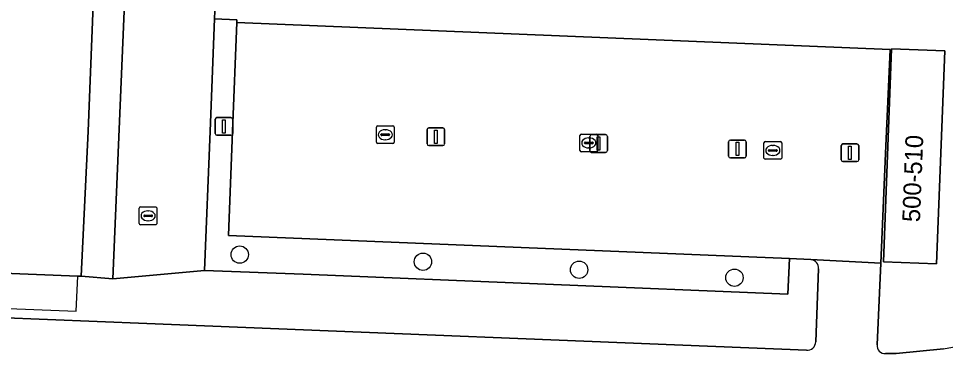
# Model space of a CAD drawing. Extents: x 160888 to 161385, y 386490 to 386908.
# Drawn here: x 160947.8 to 161000.1, y 386737.3 to 386756.3 of the extents above; entities that cross this region are included whole.
import ezdxf

# ---------------------------------------------------------------- set-up
doc = ezdxf.new("R2010")
doc.units = 0
for name, color, linetype in [('IMGEO_Boom', 7, 'Continuous'), ('IMGEO_Fietspad_gesloten', 7, 'Continuous'), ('IMGEO_Groenvoorziening', 7, 'Continuous'), ('IMGEO_Haag', 7, 'Continuous'), ('IMGEO_Kolk', 7, 'Continuous'), ('IMGEO_Lichtmast', 7, 'Continuous'), ('IMGEO_Pand', 7, 'Continuous'), ('IMGEO_Pand_nummerreeks', 7, 'Continuous'), ('IMGEO_Pand_overbouw', 7, 'Continuous'), ('IMGEO_Parkeervlak_open', 7, 'Continuous'), ('IMGEO_Voetpad_gesloten', 7, 'Continuous'), ('IMGEO_Voetpad_open', 7, 'Continuous')]:
    doc.layers.add(name, color=color, linetype=linetype)

msp = doc.modelspace()

# ---------------------------------------------------------------- linework, layer by layer
at = {"layer": 'IMGEO_Boom'}
for centre in [(160960.32, 386743.054), (160970.655, 386742.654), (160979.462, 386742.2), (160988.221, 386741.755)]:
    msp.add_circle(centre, 0.489, dxfattribs=at)
at = {"layer": 'IMGEO_Fietspad_gesloten'}
for points in [[(160996.272, 386737.982), (160996.473, 386742.58), (160992.523, 386742.772)], [(160992.965, 386742.258), (160992.803, 386738.141)], [(160992.282, 386737.671), (160955.08, 386739.168), (160921.46, 386740.524), (160922.279, 386736.94), (160925.661, 386736.849), (160955.395, 386735.634), (160990.998, 386734.2), (160994.79, 386734.023), (160998.243, 386734.057), (161000, 386734.178), (161002.436, 386734.648), (161005.984, 386735.898), (161019.969, 386741.623)], [(161000, 386737.75), (160997.335, 386737.486), (160996.739, 386737.486)]]:
    msp.add_lwpolyline(points, dxfattribs=at)
for centre, radius, start, end in [((160992.474, 386742.283), 0.492, 357.1219, 84.264), ((160996.766, 386756.848), 19.37, 279.6107, 294.7188), ((160992.328, 386738.144), 0.475, 264.4595, 359.6485), ((160996.696, 386737.913), 0.429, 170.7634, 275.7868)]:
    msp.add_arc(centre, radius, start, end, dxfattribs=at)
at = {"layer": 'IMGEO_Groenvoorziening'}
msp.add_lwpolyline([(160958.895, 386756.331), (160958.645, 386750), (160958.336, 386742.153), (160963.905, 386741.957), (160991.231, 386740.83), (160991.315, 386742.829), (160959.678, 386744.125), (160959.912, 386750), (160960.156, 386756.131), (160960.162, 386756.277)], close=True, dxfattribs=at)
at = {"layer": 'IMGEO_Haag'}
msp.add_lwpolyline([(160958.895, 386756.331), (160958.645, 386750), (160958.336, 386742.153), (160963.905, 386741.957), (160991.231, 386740.83), (160991.315, 386742.829), (160959.678, 386744.125), (160959.912, 386750), (160960.156, 386756.131), (160960.162, 386756.277)], close=True, dxfattribs=at)
at = {"layer": 'IMGEO_Kolk'}
for p, q in [((160968.027, 386749.379), (160968.027, 386750.231)), ((160968.102, 386750.305), (160968.954, 386750.305)), ((160968.329, 386749.848), (160968.727, 386749.848)), ((160968.515, 386750.085), (160968.54, 386750.085)), ((160969.028, 386750.231), (160969.028, 386749.379)), ((160979.581, 386749.845), (160980.433, 386749.845)), ((160968.286, 386749.799), (160968.286, 386749.811)), ((160968.724, 386749.762), (160968.326, 386749.762)), ((160968.538, 386749.525), (160968.513, 386749.525)), ((160968.77, 386749.811), (160968.77, 386749.799)), ((160979.506, 386748.919), (160979.506, 386749.771)), ((160979.765, 386749.339), (160979.765, 386749.351)), ((160979.808, 386749.388), (160980.206, 386749.388)), ((160979.994, 386749.625), (160980.019, 386749.625)), ((160980.249, 386749.351), (160980.249, 386749.339)), ((160980.507, 386749.771), (160980.507, 386748.919)), ((160989.884, 386748.495), (160989.884, 386749.347)), ((160989.959, 386749.421), (160990.811, 386749.421)), ((160990.885, 386749.347), (160990.885, 386748.495)), ((160968.954, 386749.305), (160968.102, 386749.305)), ((160980.433, 386748.845), (160979.581, 386748.845)), ((160980.203, 386749.302), (160979.805, 386749.302)), ((160980.017, 386749.065), (160979.992, 386749.065)), ((160990.143, 386748.915), (160990.143, 386748.927)), ((160990.581, 386748.878), (160990.183, 386748.878)), ((160990.186, 386748.964), (160990.584, 386748.964)), ((160990.372, 386749.201), (160990.397, 386749.201)), ((160990.627, 386748.927), (160990.627, 386748.915)), ((160990.811, 386748.421), (160989.959, 386748.421)), ((160990.395, 386748.641), (160990.37, 386748.641)), ((160954.654, 386744.812), (160954.654, 386745.664)), ((160954.729, 386745.738), (160955.581, 386745.738)), ((160955.655, 386745.664), (160955.655, 386744.812)), ((160954.913, 386745.232), (160954.913, 386745.244)), ((160955.351, 386745.195), (160954.953, 386745.195)), ((160954.956, 386745.281), (160955.354, 386745.281)), ((160955.142, 386745.518), (160955.167, 386745.518)), ((160955.397, 386745.244), (160955.397, 386745.232)), ((160955.581, 386744.738), (160954.729, 386744.738)), ((160955.165, 386744.958), (160955.14, 386744.958))]:
    msp.add_line(p, q, dxfattribs=at)
for points in [[(160968.027, 386749.379), (160968.027, 386750.231)], [(160968.102, 386750.305), (160968.954, 386750.305)], [(160969.028, 386750.231), (160969.028, 386749.379)], [(160979.581, 386749.845), (160980.433, 386749.845)], [(160979.506, 386748.919), (160979.506, 386749.771)], [(160980.507, 386749.771), (160980.507, 386748.919)], [(160989.884, 386748.495), (160989.884, 386749.347)], [(160989.959, 386749.421), (160990.811, 386749.421)], [(160990.885, 386749.347), (160990.885, 386748.495)], [(160968.954, 386749.305), (160968.102, 386749.305)], [(160980.433, 386748.845), (160979.581, 386748.845)], [(160990.811, 386748.421), (160989.959, 386748.421)], [(160954.654, 386744.812), (160954.654, 386745.664)], [(160954.729, 386745.738), (160955.581, 386745.738)], [(160955.655, 386745.664), (160955.655, 386744.812)], [(160955.581, 386744.738), (160954.729, 386744.738)]]:
    msp.add_lwpolyline(points, dxfattribs=at)
for centre, radius, start, end in [((160968.104, 386750.229), 0.0765, 91.552, 178.448), ((160968.104, 386750.229), 0.0765, 91.552, 178.448), ((160968.326, 386749.808), 0.0403, 85.8775, 175.7526), ((160968.731, 386749.81), 0.0386, 1.7309, 96.639), ((160968.952, 386750.229), 0.0765, 1.552, 88.448), ((160968.952, 386750.229), 0.0765, 1.552, 88.448), ((160979.583, 386749.769), 0.0765, 91.552, 178.448), ((160979.583, 386749.769), 0.0765, 91.552, 178.448), ((160980.431, 386749.769), 0.0765, 1.552, 88.448), ((160980.431, 386749.769), 0.0765, 1.552, 88.448), ((160968.104, 386749.381), 0.0765, 181.552, 268.448), ((160968.104, 386749.381), 0.0765, 181.552, 268.448), ((160968.323, 386749.798), 0.0366, 178.938, 274.7102), ((160968.727, 386749.805), 0.043, 264.8664, 352.4533), ((160968.952, 386749.381), 0.0765, 271.552, 358.448), ((160968.952, 386749.381), 0.0765, 271.552, 358.448), ((160979.805, 386749.348), 0.0403, 85.8775, 175.7526), ((160979.802, 386749.338), 0.0366, 178.938, 274.7102), ((160980.206, 386749.345), 0.043, 264.8664, 352.4533), ((160980.21, 386749.35), 0.0386, 1.7309, 96.639), ((160989.961, 386749.345), 0.0765, 91.552, 178.448), ((160989.961, 386749.345), 0.0765, 91.552, 178.448), ((160990.809, 386749.345), 0.0765, 1.552, 88.448), ((160990.809, 386749.345), 0.0765, 1.552, 88.448), ((160979.583, 386748.921), 0.0765, 181.552, 268.448), ((160979.583, 386748.921), 0.0765, 181.552, 268.448), ((160980.431, 386748.921), 0.0765, 271.552, 358.448), ((160980.431, 386748.921), 0.0765, 271.552, 358.448), ((160990.183, 386748.924), 0.0403, 85.8775, 175.7526), ((160990.18, 386748.914), 0.0366, 178.938, 274.7102), ((160990.584, 386748.921), 0.043, 264.8664, 352.4533), ((160990.588, 386748.926), 0.0386, 1.7309, 96.639), ((160989.961, 386748.497), 0.0765, 181.552, 268.448), ((160989.961, 386748.497), 0.0765, 181.552, 268.448), ((160990.809, 386748.497), 0.0765, 271.552, 358.448), ((160990.809, 386748.497), 0.0765, 271.552, 358.448), ((160954.731, 386745.662), 0.0765, 91.552, 178.448), ((160954.731, 386745.662), 0.0765, 91.552, 178.448), ((160955.579, 386745.662), 0.0765, 1.552, 88.448), ((160955.579, 386745.662), 0.0765, 1.552, 88.448), ((160954.953, 386745.241), 0.0403, 85.8775, 175.7526), ((160954.95, 386745.231), 0.0366, 178.938, 274.7102), ((160955.354, 386745.238), 0.043, 264.8664, 352.4533), ((160955.358, 386745.243), 0.0386, 1.7309, 96.639), ((160954.731, 386744.814), 0.0765, 181.552, 268.448), ((160954.731, 386744.814), 0.0765, 181.552, 268.448), ((160955.579, 386744.814), 0.0765, 271.552, 358.448), ((160955.579, 386744.814), 0.0765, 271.552, 358.448)]:
    msp.add_arc(centre, radius, start, end, dxfattribs=at)
for centre, major_axis, ratio, start_param, end_param in [((160968.514, 386749.805), (-0.387, 0.002), 0.722429, 4.712389, 7.853982), ((160968.539, 386749.805), (-0.39, 0.002), 0.717154, 1.570796, 4.712389), ((160979.993, 386749.345), (-0.387, 0.002), 0.722429, 4.712389, 7.853982), ((160980.018, 386749.345), (-0.39, 0.002), 0.717154, 1.570796, 4.712389), ((160990.371, 386748.921), (-0.387, 0.002), 0.722429, 4.712389, 7.853982), ((160990.396, 386748.921), (-0.39, 0.002), 0.717154, 1.570796, 4.712389), ((160955.141, 386745.238), (-0.387, 0.002), 0.722429, 4.712389, 7.853982), ((160955.166, 386745.238), (-0.39, 0.002), 0.717154, 1.570796, 4.712389)]:
    msp.add_ellipse(centre, major_axis=major_axis, ratio=ratio, start_param=start_param, end_param=end_param, dxfattribs=at)
at = {"layer": 'IMGEO_Lichtmast'}
for p, q in [((160958.935, 386749.873), (160958.935, 386750.673)), ((160958.935, 386750.673), (160958.935, 386749.873)), ((160959.035, 386750.773), (160959.825, 386750.773)), ((160959.825, 386750.773), (160959.035, 386750.773)), ((160959.925, 386750.673), (160959.925, 386749.873)), ((160959.925, 386749.873), (160959.925, 386750.673)), ((160970.886, 386749.294), (160970.886, 386750.094)), ((160970.886, 386750.094), (160970.886, 386749.294)), ((160970.986, 386750.194), (160971.776, 386750.194)), ((160971.776, 386750.194), (160970.986, 386750.194)), ((160971.876, 386750.094), (160971.876, 386749.294)), ((160971.876, 386749.294), (160971.876, 386750.094)), ((160959.825, 386749.773), (160959.035, 386749.773)), ((160959.035, 386749.773), (160959.825, 386749.773)), ((160980.065, 386748.911), (160980.065, 386749.711)), ((160980.065, 386749.711), (160980.065, 386748.911)), ((160980.165, 386749.811), (160980.955, 386749.811)), ((160980.955, 386749.811), (160980.165, 386749.811)), ((160981.055, 386749.711), (160981.055, 386748.911)), ((160981.055, 386748.911), (160981.055, 386749.711)), ((160987.891, 386748.603), (160987.891, 386749.403)), ((160987.891, 386749.403), (160987.891, 386748.603)), ((160987.991, 386749.503), (160988.781, 386749.503)), ((160988.781, 386749.503), (160987.991, 386749.503)), ((160988.881, 386749.403), (160988.881, 386748.603)), ((160988.881, 386748.603), (160988.881, 386749.403)), ((160971.776, 386749.194), (160970.986, 386749.194)), ((160970.986, 386749.194), (160971.776, 386749.194)), ((160980.955, 386748.811), (160980.165, 386748.811)), ((160980.165, 386748.811), (160980.955, 386748.811)), ((160994.24, 386748.393), (160994.24, 386749.193)), ((160994.24, 386749.193), (160994.24, 386748.393)), ((160994.34, 386749.293), (160995.13, 386749.293)), ((160995.13, 386749.293), (160994.34, 386749.293)), ((160995.23, 386749.193), (160995.23, 386748.393)), ((160995.23, 386748.393), (160995.23, 386749.193)), ((160988.781, 386748.503), (160987.991, 386748.503)), ((160987.991, 386748.503), (160988.781, 386748.503)), ((160995.13, 386748.293), (160994.34, 386748.293)), ((160994.34, 386748.293), (160995.13, 386748.293))]:
    msp.add_line(p, q, dxfattribs=at)
for points in [[(160959.355, 386750.648), (160959.505, 386750.648), (160959.505, 386749.898), (160959.355, 386749.898), (160959.355, 386750.648)], [(160971.306, 386750.069), (160971.456, 386750.069), (160971.456, 386749.319), (160971.306, 386749.319), (160971.306, 386750.069)], [(160980.485, 386749.686), (160980.635, 386749.686), (160980.635, 386748.936), (160980.485, 386748.936), (160980.485, 386749.686)], [(160988.311, 386749.378), (160988.461, 386749.378), (160988.461, 386748.628), (160988.311, 386748.628), (160988.311, 386749.378)], [(160994.66, 386749.168), (160994.81, 386749.168), (160994.81, 386748.418), (160994.66, 386748.418), (160994.66, 386749.168)]]:
    msp.add_lwpolyline(points, dxfattribs=at)
for centre, start, end in [((160959.035, 386750.673), 90, 180), ((160959.035, 386750.673), 90, 180), ((160959.825, 386750.673), 0, 90), ((160959.825, 386750.673), 360, 90), ((160959.035, 386749.873), 180, 270), ((160959.035, 386749.873), 180, 270), ((160959.825, 386749.873), 270, 0), ((160959.825, 386749.873), 270, 0), ((160970.986, 386750.094), 90, 180), ((160970.986, 386750.094), 90, 180), ((160971.776, 386750.094), 0, 90), ((160971.776, 386750.094), 360, 90), ((160980.165, 386749.711), 90, 180), ((160980.165, 386749.711), 90, 180), ((160980.955, 386749.711), 0, 90), ((160980.955, 386749.711), 360, 90), ((160987.991, 386749.403), 90, 180), ((160987.991, 386749.403), 90, 180), ((160988.781, 386749.403), 0, 90), ((160988.781, 386749.403), 360, 90), ((160970.986, 386749.294), 180, 270), ((160970.986, 386749.294), 180, 270), ((160971.776, 386749.294), 270, 0), ((160971.776, 386749.294), 270, 0), ((160980.165, 386748.911), 180, 270), ((160980.165, 386748.911), 180, 270), ((160980.955, 386748.911), 270, 0), ((160980.955, 386748.911), 270, 0), ((160994.34, 386749.193), 90, 180), ((160994.34, 386749.193), 90, 180), ((160995.13, 386749.193), 0, 90), ((160995.13, 386749.193), 360, 90), ((160987.991, 386748.603), 180, 270), ((160987.991, 386748.603), 180, 270), ((160988.781, 386748.603), 270, 0), ((160988.781, 386748.603), 270, 0), ((160994.34, 386748.393), 180, 270), ((160994.34, 386748.393), 180, 270), ((160995.13, 386748.393), 270, 0), ((160995.13, 386748.393), 270, 0)]:
    msp.add_arc(centre, 0.1, start, end, dxfattribs=at)
at = {"layer": 'IMGEO_Pand'}
msp.add_lwpolyline([(160932.347, 386861.777), (160929.668, 386802.21), (160931.656, 386802.139), (160931.458, 386796.556), (160930.162, 386759.955), (160932.106, 386759.876), (160931.896, 386754.732), (160931.703, 386750), (160931.403, 386742.634), (160931.578, 386742.627), (160951.188, 386741.843), (160951.385, 386741.835), (160951.772, 386750), (160952.32, 386763.778), (160952.108, 386763.787), (160950.315, 386763.859), (160951.446, 386797.676), (160949.448, 386797.758), (160951.78, 386847.873)], dxfattribs=at)
msp.add_lwpolyline([(160996.619, 386742.652), (160999.617, 386742.535), (161000.083, 386754.528), (160997.085, 386754.644)], close=True, dxfattribs=at)
at = {"layer": 'IMGEO_Pand_overbouw'}
msp.add_lwpolyline([(160931.578, 386742.627), (160931.495, 386740.644), (160951.101, 386739.86), (160951.188, 386741.843)], close=True, dxfattribs=at)
at = {"layer": 'IMGEO_Parkeervlak_open'}
msp.add_lwpolyline([(160960.156, 386756.131), (160959.912, 386750), (160959.678, 386744.125), (160991.315, 386742.829), (160992.523, 386742.772), (160996.473, 386742.58), (160996.742, 386748.751), (160996.797, 386750), (160996.998, 386754.61)], close=True, dxfattribs=at)
at = {"layer": 'IMGEO_Voetpad_gesloten'}
for points in [[(160992.523, 386742.772), (160991.315, 386742.829), (160991.231, 386740.83), (160963.905, 386741.957), (160958.336, 386742.153), (160953.158, 386741.685), (160951.385, 386741.835), (160951.188, 386741.843), (160931.578, 386742.627)], [(160992.803, 386738.141), (160992.965, 386742.258)], [(160921.46, 386740.524), (160955.08, 386739.168), (160992.282, 386737.671)]]:
    msp.add_lwpolyline(points, dxfattribs=at)
for centre, radius, start, end in [((160992.474, 386742.283), 0.492, 357.1219, 84.264), ((160992.328, 386738.144), 0.475, 264.4595, 359.6485)]:
    msp.add_arc(centre, radius, start, end, dxfattribs=at)
at = {"layer": 'IMGEO_Voetpad_open'}
for points in [[(160953.498, 386797.543), (160952.108, 386763.787), (160952.32, 386763.778), (160951.772, 386750), (160951.385, 386741.835), (160953.158, 386741.685), (160956.276, 386815.366)], [(160956.276, 386815.366), (160953.158, 386741.685), (160958.336, 386742.153), (160958.645, 386750), (160958.895, 386756.331), (160959.002, 386759.048), (160959.307, 386766.728), (160958.677, 386766.743)], [(161024.679, 386761.943), (161024.466, 386756.364), (161000, 386757.358), (160988.523, 386757.824), (160959.002, 386759.048), (160958.895, 386756.331), (160960.162, 386756.277), (160960.156, 386756.131), (160996.998, 386754.61), (160996.797, 386750), (160996.742, 386748.751), (160996.473, 386742.58), (160996.272, 386737.982)], [(160996.739, 386737.486), (160997.335, 386737.486), (161000, 386737.75)]]:
    msp.add_lwpolyline(points, dxfattribs=at)
msp.add_lwpolyline([(160999.617, 386742.535), (160996.619, 386742.652), (160997.085, 386754.644), (161000.083, 386754.528)], close=True, dxfattribs=at)
for centre, radius, start, end in [((160996.766, 386756.848), 19.37, 279.6107, 294.7188), ((160996.696, 386737.913), 0.429, 170.7634, 275.7868)]:
    msp.add_arc(centre, radius, start, end, dxfattribs=at)

# ---------------------------------------------------------------- texts
at = {"layer": 'IMGEO_Pand_nummerreeks'}
msp.add_text('500-510', height=1, rotation=87.773, dxfattribs=at).set_placement((160998.68, 386744.87))

doc.saveas('drawing.dxf')
